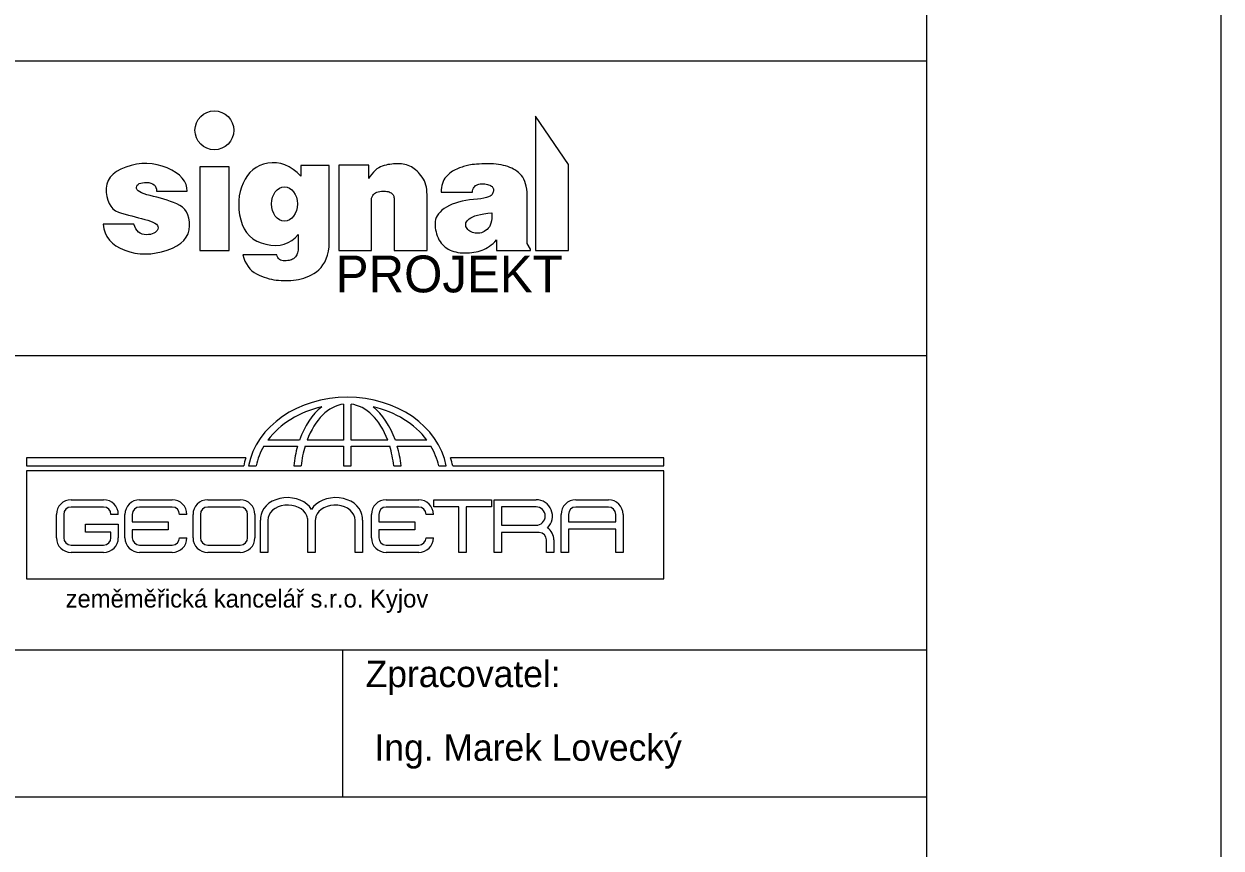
# Model space of a CAD drawing. Extents: x 1983 to 3683, y -2035 to -1591.
# Drawn here: x 2856.3 to 2937.6, y -1936.2 to -1880.3 of the extents above; entities that cross this region are included whole.
import ezdxf

# ---------------------------------------------------------------- set-up
doc = ezdxf.new("R2010")
doc.units = 0
for name, color, linetype in [('Default', 7, 'Continuous'), ('Komunikace', 7, 'Continuous'), ('Křížky', 7, 'Continuous'), ('Svazek obcí-chráničky', 7, 'Continuous'), ('Vrstva 51', 7, 'Continuous')]:
    doc.layers.add(name, color=color, linetype=linetype)

msp = doc.modelspace()

# ---------------------------------------------------------------- linework, layer by layer
at = {"layer": 'Default'}
msp.add_lwpolyline([(2727.602, -2034.752), (2937.602, -2034.752), (2937.602, -1737.752), (2727.602, -1737.752)], close=True, dxfattribs=at)
at = {"layer": 'Komunikace'}
for points in [[(2893.266, -1895.631), (2893.266, -1889.791), (2891.026, -1886.511), (2891.026, -1895.631), (2893.266, -1895.631)], [(2874.086, -1897.673), (2874.254, -1897.67), (2874.424, -1897.661), (2874.596, -1897.647), (2874.77, -1897.629), (2874.944, -1897.602), (2875.118, -1897.563), (2875.292, -1897.512), (2875.465, -1897.449), (2875.638, -1897.373), (2875.811, -1897.286), (2875.984, -1897.186), (2876.156, -1897.074), (2876.32, -1896.944), (2876.469, -1896.792), (2876.601, -1896.616), (2876.718, -1896.417), (2876.819, -1896.195), (2876.904, -1895.95), (2876.973, -1895.682), (2877.026, -1895.391), (2877.026, -1889.871), (2875.106, -1889.871), (2875.106, -1890.591), (2874.84, -1890.337), (2874.57, -1890.123), (2874.295, -1889.951), (2874.016, -1889.82), (2873.733, -1889.73), (2873.446, -1889.682), (2873.154, -1889.674), (2872.858, -1889.707), (2872.571, -1889.776), (2872.306, -1889.872), (2872.062, -1889.998), (2871.84, -1890.152), (2871.64, -1890.334), (2871.462, -1890.545), (2871.306, -1890.784), (2871.171, -1891.052), (2871.06, -1891.338), (2870.975, -1891.631), (2870.916, -1891.931), (2870.883, -1892.239), (2870.876, -1892.553), (2870.895, -1892.875), (2870.94, -1893.204), (2871.011, -1893.54), (2871.111, -1893.863), (2871.243, -1894.154), (2871.409, -1894.412), (2871.607, -1894.637), (2871.838, -1894.83), (2872.101, -1894.99), (2872.397, -1895.117), (2872.726, -1895.212), (2873.062, -1895.27), (2873.381, -1895.287), (2873.681, -1895.264), (2873.964, -1895.2), (2874.229, -1895.095), (2874.477, -1894.95), (2874.707, -1894.764), (2874.918, -1894.537), (2874.918, -1895.614), (2874.9, -1895.701), (2874.877, -1895.783), (2874.849, -1895.859), (2874.817, -1895.929), (2874.781, -1895.993), (2874.74, -1896.052), (2874.694, -1896.105), (2874.644, -1896.152), (2874.588, -1896.194), (2874.526, -1896.23), (2874.456, -1896.261), (2874.379, -1896.287), (2874.295, -1896.307), (2874.204, -1896.322), (2874.106, -1896.331), (2874.001, -1896.335), (2873.897, -1896.33), (2873.804, -1896.311), (2873.72, -1896.279), (2873.647, -1896.234), (2873.584, -1896.176), (2873.532, -1896.104), (2873.489, -1896.019), (2873.457, -1895.921), (2871.15, -1895.921), (2871.219, -1896.149), (2871.302, -1896.358), (2871.399, -1896.548), (2871.51, -1896.719), (2871.635, -1896.872), (2871.773, -1897.006), (2871.926, -1897.121), (2872.092, -1897.217), (2872.264, -1897.3), (2872.435, -1897.374), (2872.604, -1897.44), (2872.772, -1897.497), (2872.938, -1897.545), (2873.103, -1897.585), (2873.266, -1897.616), (2873.428, -1897.639), (2873.59, -1897.655), (2873.753, -1897.666), (2873.919, -1897.672), (2874.086, -1897.673)], [(2864.538, -1895.866), (2864.9, -1895.849), (2865.266, -1895.802), (2865.637, -1895.723), (2866.013, -1895.612), (2866.368, -1895.476), (2866.676, -1895.32), (2866.937, -1895.144), (2867.151, -1894.948), (2867.318, -1894.732), (2867.439, -1894.496), (2867.512, -1894.24), (2867.539, -1893.964), (2867.528, -1893.691), (2867.49, -1893.442), (2867.424, -1893.218), (2867.33, -1893.018), (2867.209, -1892.844), (2867.059, -1892.694), (2866.882, -1892.568), (2866.678, -1892.467), (2866.458, -1892.381), (2866.236, -1892.3), (2866.012, -1892.222), (2865.786, -1892.149), (2865.557, -1892.081), (2865.326, -1892.017), (2865.092, -1891.957), (2864.857, -1891.902), (2864.635, -1891.847), (2864.444, -1891.787), (2864.283, -1891.724), (2864.153, -1891.657), (2864.053, -1891.586), (2863.983, -1891.511), (2863.944, -1891.432), (2863.936, -1891.349), (2863.952, -1891.269), (2863.989, -1891.2), (2864.045, -1891.142), (2864.121, -1891.095), (2864.217, -1891.059), (2864.332, -1891.033), (2864.468, -1891.019), (2864.623, -1891.015), (2864.778, -1891.026), (2864.914, -1891.055), (2865.029, -1891.102), (2865.123, -1891.168), (2865.198, -1891.252), (2865.253, -1891.354), (2865.287, -1891.474), (2865.302, -1891.613), (2867.381, -1891.613), (2867.361, -1891.372), (2867.299, -1891.142), (2867.194, -1890.925), (2867.046, -1890.72), (2866.856, -1890.529), (2866.622, -1890.35), (2866.345, -1890.184), (2866.026, -1890.031), (2865.684, -1889.901), (2865.339, -1889.807), (2864.991, -1889.747), (2864.641, -1889.722), (2864.288, -1889.732), (2863.932, -1889.777), (2863.574, -1889.856), (2863.213, -1889.971), (2862.875, -1890.113), (2862.586, -1890.276), (2862.345, -1890.46), (2862.153, -1890.663), (2862.009, -1890.888), (2861.915, -1891.133), (2861.868, -1891.398), (2861.871, -1891.684), (2861.91, -1891.965), (2861.976, -1892.217), (2862.069, -1892.44), (2862.187, -1892.633), (2862.332, -1892.796), (2862.503, -1892.93), (2862.7, -1893.034), (2862.923, -1893.109), (2863.158, -1893.169), (2863.389, -1893.228), (2863.617, -1893.288), (2863.841, -1893.347), (2864.061, -1893.405), (2864.278, -1893.464), (2864.491, -1893.522), (2864.701, -1893.579), (2864.893, -1893.639), (2865.054, -1893.704), (2865.185, -1893.773), (2865.284, -1893.846), (2865.353, -1893.924), (2865.391, -1894.006), (2865.398, -1894.093), (2865.374, -1894.185), (2865.327, -1894.273), (2865.266, -1894.349), (2865.191, -1894.414), (2865.101, -1894.467), (2864.997, -1894.508), (2864.878, -1894.538), (2864.745, -1894.556), (2864.598, -1894.563), (2864.45, -1894.553), (2864.314, -1894.52), (2864.19, -1894.464), (2864.079, -1894.385), (2863.98, -1894.284), (2863.894, -1894.16), (2863.82, -1894.014), (2863.758, -1893.846), (2861.678, -1893.846), (2861.722, -1894.152), (2861.805, -1894.434), (2861.928, -1894.692), (2862.091, -1894.926), (2862.293, -1895.135), (2862.535, -1895.32), (2862.816, -1895.481), (2863.137, -1895.618), (2863.48, -1895.727), (2863.828, -1895.805), (2864.181, -1895.851), (2864.538, -1895.866)], [(2870.226, -1895.631), (2870.226, -1889.951), (2868.226, -1889.951), (2868.226, -1895.631), (2870.226, -1895.631)], [(2883.666, -1895.631), (2883.666, -1891.831), (2883.663, -1891.661), (2883.649, -1891.498), (2883.624, -1891.341), (2883.589, -1891.191), (2883.543, -1891.048), (2883.486, -1890.911), (2883.418, -1890.78), (2883.339, -1890.657), (2883.254, -1890.54), (2883.167, -1890.432), (2883.078, -1890.332), (2882.987, -1890.241), (2882.894, -1890.157), (2882.799, -1890.082), (2882.702, -1890.015), (2882.603, -1889.956), (2882.501, -1889.905), (2882.395, -1889.861), (2882.284, -1889.823), (2882.169, -1889.793), (2882.049, -1889.769), (2881.926, -1889.753), (2881.798, -1889.743), (2881.666, -1889.74), (2881.532, -1889.743), (2881.399, -1889.752), (2881.268, -1889.765), (2881.138, -1889.783), (2881.009, -1889.805), (2880.881, -1889.833), (2880.754, -1889.866), (2880.629, -1889.904), (2880.505, -1889.952), (2880.384, -1890.017), (2880.265, -1890.098), (2880.149, -1890.196), (2880.034, -1890.31), (2879.923, -1890.44), (2879.813, -1890.587), (2879.706, -1890.751), (2879.706, -1889.831), (2877.666, -1889.831), (2877.666, -1895.631), (2879.906, -1895.631), (2879.906, -1892.071), (2879.941, -1891.98), (2879.985, -1891.899), (2880.039, -1891.828), (2880.104, -1891.767), (2880.178, -1891.716), (2880.262, -1891.675), (2880.356, -1891.644), (2880.46, -1891.623), (2880.566, -1891.61), (2880.666, -1891.603), (2880.762, -1891.602), (2880.852, -1891.608), (2880.937, -1891.619), (2881.017, -1891.637), (2881.091, -1891.66), (2881.16, -1891.69), (2881.223, -1891.725), (2881.277, -1891.763), (2881.322, -1891.805), (2881.36, -1891.851), (2881.389, -1891.9), (2881.41, -1891.954), (2881.422, -1892.01), (2881.426, -1892.071), (2881.426, -1895.631), (2883.666, -1895.631)], [(2886.229, -1895.795), (2886.391, -1895.792), (2886.548, -1895.784), (2886.702, -1895.769), (2886.851, -1895.749), (2886.995, -1895.723), (2887.135, -1895.692), (2887.271, -1895.654), (2887.403, -1895.611), (2887.532, -1895.56), (2887.659, -1895.499), (2887.784, -1895.427), (2887.908, -1895.344), (2888.03, -1895.252), (2888.15, -1895.148), (2888.269, -1895.035), (2888.386, -1894.911), (2888.386, -1895.631), (2890.706, -1895.631), (2890.706, -1895.551), (2890.466, -1895.151), (2890.466, -1891.671), (2890.44, -1891.466), (2890.404, -1891.276), (2890.359, -1891.101), (2890.304, -1890.939), (2890.239, -1890.793), (2890.165, -1890.66), (2890.082, -1890.542), (2889.989, -1890.439), (2889.888, -1890.346), (2889.78, -1890.261), (2889.667, -1890.182), (2889.547, -1890.11), (2889.421, -1890.045), (2889.288, -1889.987), (2889.15, -1889.936), (2889.005, -1889.891), (2888.853, -1889.854), (2888.694, -1889.821), (2888.527, -1889.795), (2888.354, -1889.774), (2888.173, -1889.759), (2887.985, -1889.75), (2887.79, -1889.746), (2887.588, -1889.748), (2887.389, -1889.754), (2887.205, -1889.763), (2887.036, -1889.773), (2886.881, -1889.786), (2886.741, -1889.801), (2886.616, -1889.818), (2886.506, -1889.837), (2886.41, -1889.859), (2886.322, -1889.883), (2886.232, -1889.908), (2886.142, -1889.936), (2886.051, -1889.966), (2885.96, -1889.997), (2885.868, -1890.031), (2885.775, -1890.066), (2885.682, -1890.103), (2885.589, -1890.145), (2885.496, -1890.194), (2885.405, -1890.249), (2885.315, -1890.311), (2885.226, -1890.38), (2885.138, -1890.456), (2885.05, -1890.539), (2884.964, -1890.628), (2884.884, -1890.726), (2884.815, -1890.833), (2884.756, -1890.949), (2884.709, -1891.075), (2884.672, -1891.21), (2884.646, -1891.354), (2884.631, -1891.508), (2884.626, -1891.671), (2886.746, -1891.671), (2886.762, -1891.575), (2886.786, -1891.487), (2886.819, -1891.409), (2886.86, -1891.34), (2886.91, -1891.281), (2886.969, -1891.23), (2887.036, -1891.189), (2887.112, -1891.157), (2887.193, -1891.132), (2887.274, -1891.114), (2887.355, -1891.103), (2887.437, -1891.098), (2887.52, -1891.1), (2887.603, -1891.108), (2887.687, -1891.123), (2887.771, -1891.144), (2887.851, -1891.17), (2887.923, -1891.198), (2887.985, -1891.228), (2888.039, -1891.26), (2888.084, -1891.294), (2888.121, -1891.33), (2888.148, -1891.369), (2888.167, -1891.409), (2888.178, -1891.452), (2888.183, -1891.498), (2888.182, -1891.546), (2888.175, -1891.598), (2888.161, -1891.652), (2888.141, -1891.709), (2888.115, -1891.769), (2888.082, -1891.831), (2888.032, -1891.893), (2887.951, -1891.948), (2887.839, -1891.999), (2887.698, -1892.045), (2887.526, -1892.085), (2887.323, -1892.119), (2887.091, -1892.149), (2886.828, -1892.173), (2886.556, -1892.2), (2886.296, -1892.237), (2886.049, -1892.285), (2885.814, -1892.343), (2885.591, -1892.412), (2885.381, -1892.492), (2885.183, -1892.582), (2884.997, -1892.683), (2884.828, -1892.791), (2884.679, -1892.903), (2884.552, -1893.021), (2884.445, -1893.142), (2884.36, -1893.268), (2884.295, -1893.399), (2884.251, -1893.534), (2884.228, -1893.674), (2884.22, -1893.815), (2884.221, -1893.956), (2884.231, -1894.095), (2884.25, -1894.232), (2884.278, -1894.369), (2884.315, -1894.505), (2884.361, -1894.639), (2884.416, -1894.772), (2884.479, -1894.9), (2884.549, -1895.019), (2884.626, -1895.13), (2884.709, -1895.231), (2884.8, -1895.324), (2884.898, -1895.408), (2885.002, -1895.483), (2885.114, -1895.549), (2885.232, -1895.606), (2885.356, -1895.656), (2885.486, -1895.699), (2885.622, -1895.733), (2885.765, -1895.76), (2885.913, -1895.78), (2886.068, -1895.791), (2886.229, -1895.795)], [(2886.945, -1894.451), (2886.842, -1894.43), (2886.747, -1894.402), (2886.66, -1894.366), (2886.581, -1894.322), (2886.511, -1894.271), (2886.448, -1894.212), (2886.393, -1894.145), (2886.346, -1894.071), (2886.312, -1893.993), (2886.294, -1893.916), (2886.293, -1893.84), (2886.308, -1893.765), (2886.341, -1893.691), (2886.39, -1893.617), (2886.456, -1893.545), (2886.538, -1893.474), (2886.642, -1893.405), (2886.77, -1893.342), (2886.924, -1893.285), (2887.103, -1893.232), (2887.307, -1893.185), (2887.537, -1893.143), (2887.791, -1893.107), (2888.071, -1893.075), (2888.075, -1893.274), (2888.067, -1893.456), (2888.045, -1893.622), (2888.01, -1893.772), (2887.963, -1893.905), (2887.902, -1894.023), (2887.829, -1894.124), (2887.743, -1894.209), (2887.649, -1894.28), (2887.554, -1894.34), (2887.457, -1894.388), (2887.358, -1894.424), (2887.257, -1894.448), (2887.155, -1894.46), (2887.051, -1894.461), (2886.945, -1894.451)]]:
    msp.add_lwpolyline(points, dxfattribs=at)
msp.add_circle((2869.226, -1887.471), 1.32, dxfattribs=at)
msp.add_ellipse((2873.986, -1892.471), major_axis=(0, 1.16), ratio=0.758621, dxfattribs=at)
at = {"layer": 'Křížky'}
msp.add_lwpolyline([(2747.602, -1757.752), (2917.602, -1757.752), (2917.602, -2017.752), (2747.602, -2017.752)], close=True, dxfattribs=at)
at = {"layer": 'Svazek obcí-chráničky'}
for p, q in [((2877.997, -1906.064), (2877.997, -1908.51)), ((2878.504, -1908.51), (2878.504, -1906.062)), ((2872.583, -1908.922), (2874.871, -1908.922)), ((2875.003, -1908.51), (2872.858, -1908.51)), ((2875.381, -1908.922), (2877.997, -1908.922)), ((2877.997, -1908.51), (2875.52, -1908.51)), ((2877.997, -1908.922), (2877.997, -1910.242)), ((2880.998, -1908.51), (2878.504, -1908.51)), ((2878.504, -1910.242), (2878.504, -1908.922)), ((2878.504, -1908.922), (2881.138, -1908.922)), ((2883.66, -1908.51), (2881.515, -1908.51)), ((2881.648, -1908.922), (2883.935, -1908.922)), ((2871.352, -1909.711), (2856.472, -1909.711)), ((2856.472, -1909.711), (2856.472, -1910.242)), ((2899.75, -1909.711), (2885.272, -1909.711)), ((2899.75, -1910.242), (2899.75, -1909.711)), ((2899.749, -1910.587), (2856.466, -1910.587)), ((2856.466, -1910.587), (2856.466, -1917.925)), ((2856.472, -1910.242), (2871.215, -1910.242)), ((2871.54, -1910.242), (2872.057, -1910.242)), ((2874.614, -1910.242), (2875.114, -1910.242)), ((2877.997, -1910.242), (2878.504, -1910.242)), ((2881.405, -1910.242), (2881.905, -1910.242)), ((2884.461, -1910.242), (2884.978, -1910.242)), ((2885.41, -1910.242), (2899.75, -1910.242)), ((2899.749, -1917.925), (2899.749, -1910.587)), ((2859.491, -1912.553), (2861.701, -1912.553)), ((2861.701, -1913.051), (2859.491, -1913.051)), ((2864.147, -1912.553), (2866.358, -1912.553)), ((2866.358, -1913.051), (2864.147, -1913.051)), ((2868.771, -1912.553), (2870.981, -1912.553)), ((2870.981, -1913.051), (2868.771, -1913.051)), ((2880.889, -1912.553), (2883.1, -1912.553)), ((2883.1, -1913.051), (2880.889, -1913.051)), ((2885.832, -1916.134), (2885.832, -1913.039)), ((2886.336, -1913.039), (2886.336, -1916.134)), ((2888.227, -1912.553), (2891.071, -1912.553)), ((2891.071, -1913.041), (2888.731, -1913.041)), ((2888.731, -1913.041), (2888.731, -1914.291)), ((2893.775, -1912.553), (2895.986, -1912.553)), ((2895.986, -1913.051), (2893.775, -1913.051)), ((2858.493, -1915.137), (2858.493, -1913.55)), ((2858.992, -1913.55), (2858.992, -1915.137)), ((2862.699, -1913.55), (2862.2, -1913.55)), ((2863.149, -1915.137), (2863.149, -1913.55)), ((2863.648, -1913.55), (2863.648, -1914.061)), ((2863.648, -1914.061), (2866.091, -1914.061)), ((2866.091, -1914.061), (2866.091, -1914.606)), ((2867.355, -1913.55), (2866.857, -1913.55)), ((2867.773, -1915.137), (2867.773, -1913.55)), ((2868.272, -1913.55), (2868.272, -1915.137)), ((2871.481, -1915.137), (2871.481, -1913.55)), ((2871.979, -1913.55), (2871.979, -1915.137)), ((2872.352, -1916.134), (2872.352, -1913.949)), ((2872.852, -1913.949), (2872.852, -1916.134)), ((2875.572, -1916.134), (2875.572, -1913.949)), ((2876.072, -1913.949), (2876.072, -1916.134)), ((2878.791, -1916.134), (2878.791, -1913.949)), ((2879.291, -1913.949), (2879.291, -1916.134)), ((2879.892, -1915.137), (2879.892, -1913.55)), ((2880.39, -1913.55), (2880.39, -1914.061)), ((2880.39, -1914.061), (2882.833, -1914.061)), ((2882.833, -1914.061), (2882.833, -1914.606)), ((2884.098, -1913.55), (2883.599, -1913.55)), ((2892.777, -1916.134), (2892.777, -1913.55)), ((2893.276, -1913.55), (2893.276, -1914.059)), ((2893.276, -1914.059), (2896.485, -1914.059)), ((2896.485, -1914.059), (2896.485, -1913.55)), ((2896.983, -1913.55), (2896.983, -1916.134)), ((2860.466, -1914.758), (2860.466, -1914.214)), ((2860.466, -1914.214), (2862.699, -1914.214)), ((2862.2, -1914.758), (2860.466, -1914.758)), ((2862.2, -1915.137), (2862.2, -1914.758)), ((2862.699, -1914.214), (2862.699, -1915.137)), ((2866.091, -1914.606), (2863.648, -1914.606)), ((2863.648, -1914.606), (2863.648, -1915.137)), ((2882.833, -1914.606), (2880.39, -1914.606)), ((2880.39, -1914.606), (2880.39, -1915.137)), ((2888.731, -1914.291), (2891.071, -1914.291)), ((2891.071, -1914.78), (2888.731, -1914.78)), ((2891.285, -1914.784), (2891.071, -1914.78)), ((2896.485, -1914.563), (2893.276, -1914.563)), ((2893.276, -1914.563), (2893.276, -1916.134)), ((2896.485, -1916.134), (2896.485, -1914.563)), ((2859.491, -1915.636), (2861.701, -1915.636)), ((2864.147, -1915.636), (2866.358, -1915.636)), ((2866.857, -1915.137), (2867.355, -1915.137)), ((2868.771, -1915.636), (2870.981, -1915.636)), ((2880.889, -1915.636), (2883.1, -1915.636)), ((2883.599, -1915.137), (2884.098, -1915.137)), ((2891.784, -1916.134), (2891.784, -1915.283)), ((2892.283, -1915.283), (2892.283, -1916.134)), ((2861.701, -1916.134), (2859.491, -1916.134)), ((2866.358, -1916.134), (2864.147, -1916.134)), ((2870.981, -1916.134), (2868.771, -1916.134)), ((2872.852, -1916.134), (2872.352, -1916.134)), ((2876.072, -1916.134), (2875.572, -1916.134)), ((2879.291, -1916.134), (2878.791, -1916.134)), ((2883.1, -1916.134), (2880.889, -1916.134)), ((2886.336, -1916.134), (2885.832, -1916.134)), ((2892.283, -1916.134), (2891.784, -1916.134)), ((2893.276, -1916.134), (2892.777, -1916.134)), ((2896.983, -1916.134), (2896.485, -1916.134)), ((2856.466, -1917.925), (2899.749, -1917.925))]:
    msp.add_line(p, q, dxfattribs=at)
for points in [[(2885.832, -1913.039), (2884.134, -1913.039), (2884.134, -1912.553), (2888.048, -1912.553)], [(2888.048, -1912.553), (2888.048, -1913.039), (2886.336, -1913.039)], [(2888.731, -1914.78), (2888.731, -1916.134), (2888.227, -1916.134), (2888.227, -1912.553)]]:
    msp.add_lwpolyline(points, dxfattribs=at)
for centre, radius, start, end in [((2859.491, -1913.55), 0.998, 90, 180), ((2859.491, -1913.55), 0.499, 90, 180), ((2861.701, -1913.55), 0.998, 360, 90), ((2861.701, -1913.55), 0.499, 0, 90), ((2864.147, -1913.55), 0.998, 90, 180), ((2864.147, -1913.55), 0.499, 90, 180), ((2866.358, -1913.55), 0.998, 360, 90), ((2866.358, -1913.55), 0.499, 0, 90), ((2868.771, -1913.55), 0.998, 90, 180), ((2868.771, -1913.55), 0.499, 90, 180), ((2870.981, -1913.55), 0.998, 360, 90), ((2870.981, -1913.55), 0.499, 0, 90), ((2880.889, -1913.55), 0.998, 90, 180), ((2880.889, -1913.55), 0.499, 90, 180), ((2883.1, -1913.55), 0.998, 360, 90), ((2883.1, -1913.55), 0.499, 0, 90), ((2891.071, -1913.666), 1.114, 314.45734, 90), ((2891.071, -1913.666), 0.625, 270, 90), ((2893.775, -1913.55), 0.998, 90, 180), ((2893.775, -1913.55), 0.499, 90, 180), ((2895.986, -1913.55), 0.998, 360, 90), ((2895.986, -1913.55), 0.499, 0, 90), ((2874.289, -1913.999), 1.938, 166.96576, 178.52091), ((2874.617, -1914.014), 0.957, 3.86486, 22.41569), ((2877.305, -1914.071), 1.238, 162.61388, 174.3506), ((2877.354, -1913.999), 1.938, 1.47909, 13.03424), ((2891.285, -1915.283), 0.499, 0, 90), ((2891.285, -1915.283), 0.998, 360, 55.44734), ((2859.491, -1915.137), 0.998, 180, 270), ((2859.491, -1915.137), 0.499, 180, 270), ((2861.701, -1915.137), 0.998, 270, 0), ((2861.701, -1915.137), 0.499, 270, 0), ((2864.147, -1915.137), 0.998, 180, 270), ((2864.147, -1915.137), 0.499, 180, 270), ((2866.358, -1915.137), 0.998, 270, 0), ((2866.358, -1915.137), 0.499, 270, 0), ((2868.771, -1915.137), 0.998, 180, 270), ((2868.771, -1915.137), 0.499, 180, 270), ((2870.981, -1915.137), 0.998, 270, 0), ((2870.981, -1915.137), 0.499, 270, 0), ((2880.889, -1915.137), 0.998, 180, 270), ((2880.889, -1915.137), 0.499, 180, 270), ((2883.1, -1915.137), 0.998, 270, 0), ((2883.1, -1915.137), 0.499, 270, 0)]:
    msp.add_arc(centre, radius, start, end, dxfattribs=at)
for centre, major_axis, ratio, start_param, end_param in [((2878.259, -1911.115), (-6.804, 0), 0.811768, 3.300239, 6.124539), ((2878.259, -1911.115), (-6.296, 0), 0.804826, 4.992897, 5.743383), ((2878.259, -1911.115), (0, 5.524), 0.668443, 0.491666, 1.079789), ((2878.259, -1911.115), (0, 5.067), 0.630136, 0.08224, 1.030995), ((2878.259, -1911.115), (0, 5.067), 0.630136, 5.252191, 6.206521), ((2878.259, -1911.115), (0, 5.524), 0.668443, 5.203397, 5.79152), ((2878.259, -1911.115), (-6.296, 0), 0.804826, 3.681394, 4.431881), ((2878.259, -1911.115), (-6.296, 0), 0.804826, 5.835664, 6.110118), ((2878.259, -1911.115), (0, 5.524), 0.668443, 1.16256, 1.41215), ((2878.259, -1911.115), (0, 5.067), 0.630136, 1.123275, 1.397729), ((2878.259, -1911.115), (0, 5.067), 0.630136, 4.885456, 5.159911), ((2878.259, -1911.115), (0, 5.524), 0.668443, 4.871035, 5.120625), ((2878.259, -1911.115), (-6.296, 0), 0.804826, 3.31466, 3.589114), ((2877.933, -1911.115), (-6.804, 0), 0.811768, 6.026233, 6.124539), ((2878.691, -1911.115), (-6.804, 0), 0.811768, 3.300239, 3.398545), ((2874.181, -1913.794), (1.805, 0), 0.766187, 0.429647, 2.97338), ((2877.462, -1913.794), (-1.805, 0), 0.766187, 3.309805, 5.853538), ((2874.206, -1913.949), (1.354, 0), 0.766187, 0.29376, 3.141593), ((2877.437, -1913.949), (-1.354, 0), 0.766187, 3.141593, 6.041607)]:
    msp.add_ellipse(centre, major_axis=major_axis, ratio=ratio, start_param=start_param, end_param=end_param, dxfattribs=at)
at = {"layer": 'Vrstva 51'}
for p, q in [((2747.602, -1902.752), (2917.602, -1902.752)), ((2747.602, -1922.752), (2917.602, -1922.752)), ((2877.952, -1932.752), (2877.952, -1922.752))]:
    msp.add_line(p, q, dxfattribs=at)
msp.add_lwpolyline([(2747.602, -1882.752), (2917.602, -1882.752), (2917.602, -1932.752), (2747.602, -1932.752)], close=True, dxfattribs=at)

# ---------------------------------------------------------------- texts
at = {"layer": 'Komunikace'}
msp.add_text('PROJEKT', height=2.5, dxfattribs=at).set_placement((2877.467, -1898.474))
at = {"layer": 'Svazek obcí-chráničky'}
msp.add_text('zeměměřická kancelář s.r.o. Kyjov', height=1.20984, dxfattribs=at).set_placement((2859.117, -1919.874))
at = {"layer": 'Vrstva 51'}
for s, p in [('Zpracovatel:', (2879.498, -1925.278)), ('Ing. Marek Lovecký', (2880.099, -1930.278))]:
    msp.add_text(s, height=1.8, dxfattribs=at).set_placement(p)

doc.saveas('drawing.dxf')
